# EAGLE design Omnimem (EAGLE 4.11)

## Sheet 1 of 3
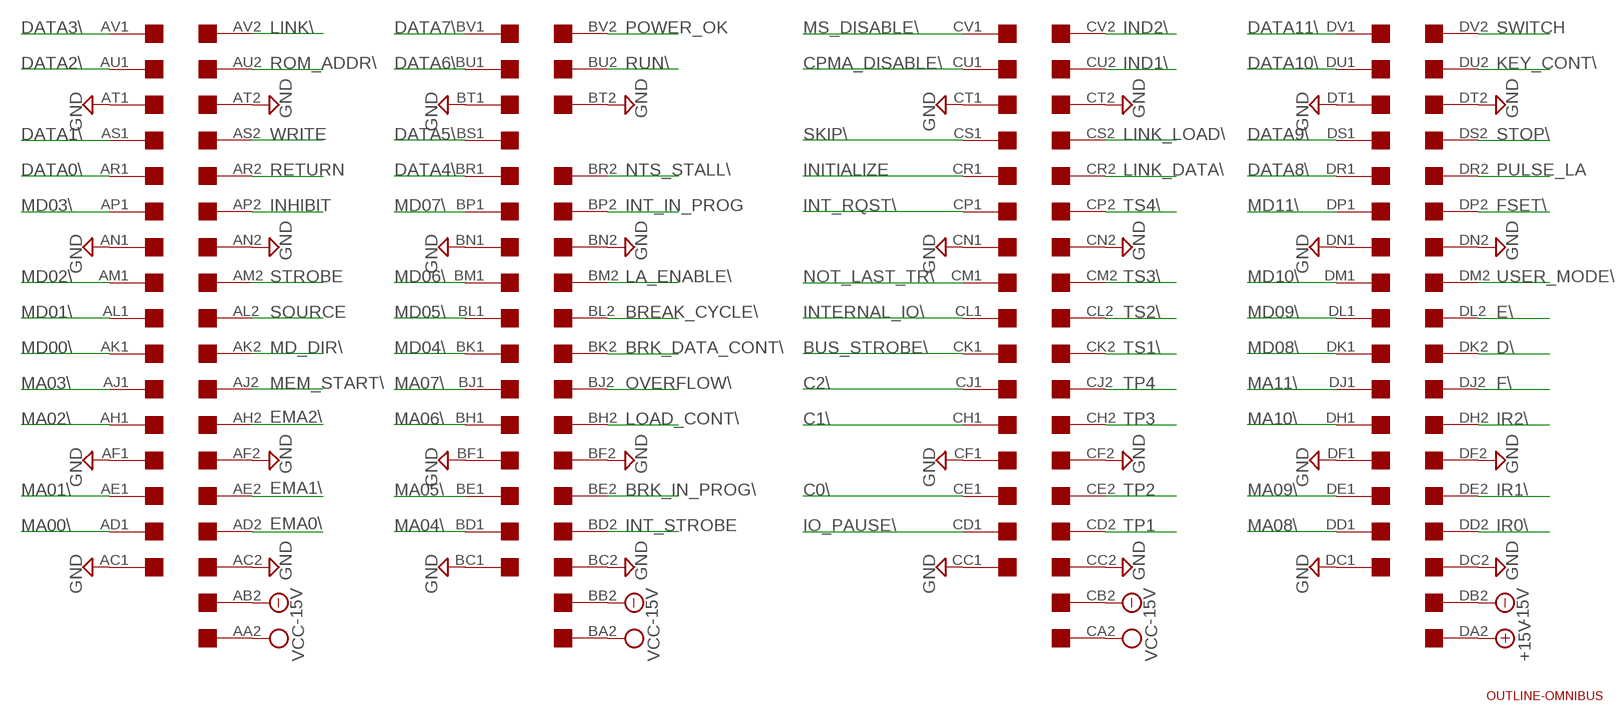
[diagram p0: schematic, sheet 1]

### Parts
U$1  OUTLINE-OMNIBUS  [OMNIBUS]
U$2  QUAD  [EDGE-CON8]

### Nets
+15V: U$2.DA2
-15V [supply]: U$2.AB2 U$2.BB2 U$2.CB2 U$2.DB2
BREAK_CYCLE\: U$2.BL2
BRK_DATA_CONT\: U$2.BK2
BRK_IN_PROG\: U$2.BE2
BUS_STROBE\: U$2.CK1
C0\: U$2.CE1
C1\: U$2.CH1
C2\: U$2.CJ1
CPMA_DISABLE\: U$2.CU1
D\: U$2.DK2
DATA0\: U$2.AR1
DATA1\: U$2.AS1
DATA2\: U$2.AU1
DATA3\: U$2.AV1
DATA4\: U$2.BR1
DATA5\: U$2.BS1
DATA6\: U$2.BU1
DATA7\: U$2.BV1
DATA8\: U$2.DR1
DATA9\: U$2.DS1
DATA10\: U$2.DU1
DATA11\: U$2.DV1
E\: U$2.DL2
EMA0\: U$2.AD2 ; also sheet 2
EMA1\: U$2.AE2 ; also sheet 2
EMA2\: U$2.AH2 ; also sheet 2
F\: U$2.DJ2
FSET\: U$2.DP2
GND [supply]: U$2.AC1 U$2.AC2 U$2.AF1 U$2.AF2 U$2.AN1 U$2.AN2 U$2.AT1 U$2.AT2 U$2.BC1 U$2.BC2 U$2.BF1 U$2.BF2 U$2.BN1 U$2.BN2 U$2.BT1 U$2.BT2 U$2.CC1 U$2.CC2 U$2.CF1 U$2.CF2 U$2.CN1 U$2.CN2 U$2.CT1 U$2.CT2 U$2.DC1 U$2.DC2 U$2.DF1 U$2.DF2 U$2.DN1 U$2.DN2 U$2.DT1 U$2.DT2 ; also sheet 2,3
IND1\: U$2.CU2
IND2\: U$2.CV2
INHIBIT: U$2.AP2
INITIALIZE: U$2.CR1
INT_IN_PROG: U$2.BP2
INT_RQST\: U$2.CP1
INT_STROBE: U$2.BD2
INTERNAL_IO\: U$2.CL1
IO_PAUSE\: U$2.CD1
IR0\: U$2.DD2
IR1\: U$2.DE2
IR2\: U$2.DH2
KEY_CONT\: U$2.DU2
LA_ENABLE\: U$2.BM2
LINK\: U$2.AV2
LINK_DATA\: U$2.CR2
LINK_LOAD\: U$2.CS2
LOAD_CONT\: U$2.BH2
MA00\: U$2.AD1 ; also sheet 2
MA01\: U$2.AE1 ; also sheet 2
MA02\: U$2.AH1 ; also sheet 2
MA03\: U$2.AJ1 ; also sheet 2
MA04\: U$2.BD1 ; also sheet 2
MA05\: U$2.BE1 ; also sheet 2
MA06\: U$2.BH1 ; also sheet 2
MA07\: U$2.BJ1 ; also sheet 2
MA08\: U$2.DD1 ; also sheet 2
MA09\: U$2.DE1 ; also sheet 2
MA10\: U$2.DH1 ; also sheet 2
MA11\: U$2.DJ1 ; also sheet 2
MD00\: U$2.AK1 ; also sheet 2
MD01\: U$2.AL1 ; also sheet 2
MD02\: U$2.AM1 ; also sheet 2
MD03\: U$2.AP1 ; also sheet 2
MD04\: U$2.BK1 ; also sheet 2
MD05\: U$2.BL1 ; also sheet 2
MD06\: U$2.BM1 ; also sheet 2
MD07\: U$2.BP1 ; also sheet 2
MD08\: U$2.DK1 ; also sheet 2
MD09\: U$2.DL1 ; also sheet 2
MD10\: U$2.DM1 ; also sheet 2
MD11\: U$2.DP1 ; also sheet 2
MD_DIR\: U$2.AK2
MEM_START\: U$2.AJ2
MS_DISABLE\: U$2.CV1
NOT_LAST_TR\: U$2.CM1
NTS_STALL\: U$2.BR2
OVERFLOW\: U$2.BJ2
POWER_OK: U$2.BV2
PULSE_LA: U$2.DR2
RETURN: U$2.AR2
ROM_ADDR\: U$2.AU2 ; also sheet 2
RUN\: U$2.BU2
SKIP\: U$2.CS1
SOURCE: U$2.AL2
STOP\: U$2.DS2
STROBE: U$2.AM2
SWITCH: U$2.DV2
TP1: U$2.CD2
TP2: U$2.CE2
TP3: U$2.CH2
TP4: U$2.CJ2
TS1\: U$2.CK2
TS2\: U$2.CL2
TS3\: U$2.CM2
TS4\: U$2.CP2
USER_MODE\: U$2.DM2
VCC [supply]: U$2.AA2 U$2.BA2 U$2.CA2 ; also sheet 2
WRITE: U$2.AS2 ; also sheet 2
Unconnected: U$2.AA1 U$2.AB1 U$2.BA1 U$2.BB1 U$2.BS2 U$2.CA1 U$2.CB1 U$2.DA1 U$2.DB1

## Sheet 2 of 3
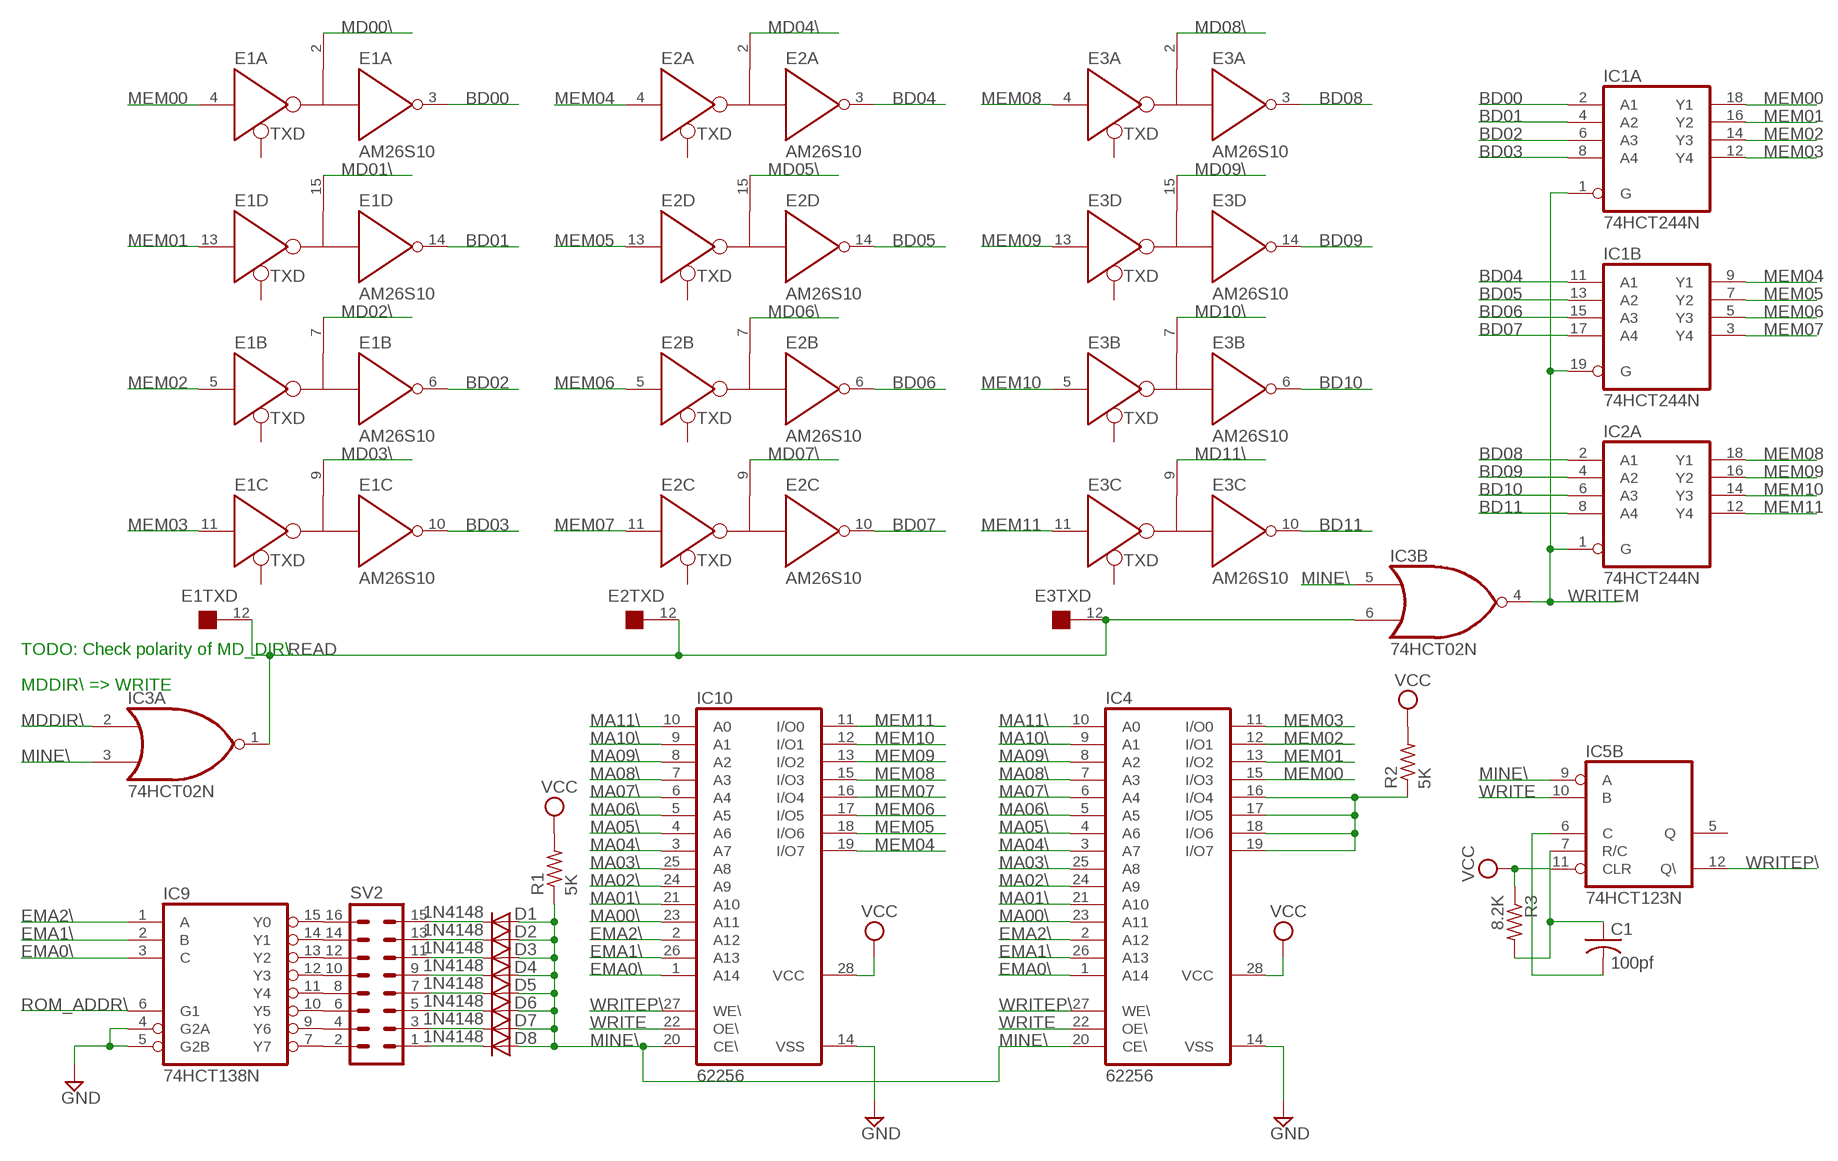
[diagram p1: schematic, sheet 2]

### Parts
C1  100pf  C-US050-025X075  [C050-025X075]
D1  1N4148  [DO35-10]
D2  1N4148  [DO35-10]
D3  1N4148  [DO35-10]
D4  1N4148  [DO35-10]
D5  1N4148  [DO35-10]
D6  1N4148  [DO35-10]
D7  1N4148  [DO35-10]
D8  1N4148  [DO35-10]
E1  AM26S10  [DIL16]
E2  AM26S10  [DIL16]
E3  AM26S10  [DIL16]
IC1  74HCT244N  [DIL20]
IC2  74HCT244N  [DIL20]
IC3  74HCT02N  [DIL14]
IC4  62256  58C256P  [DIL28-6]
IC5  74HCT123N  [DIL16]
IC9  74HCT138N  [DIL16]
IC10  62256  58C256P  [DIL28-6]
R1  5K  R-US_0207/10  [0207/10]
R2  5K  R-US_0207/10  [0207/10]
R3  8.2K  R-US_0207/10  [0207/10]
SV2  MA08-2  [MA08-2]

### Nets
BD00: E1.3(A:R) IC1.2(A:A1)
BD01: E1.14(D:R) IC1.4(A:A2)
BD02: E1.6(B:R) IC1.6(A:A3)
BD03: E1.10(C:R) IC1.8(A:A4)
BD04: E2.3(A:R) IC1.11(B:A1)
BD05: E2.14(D:R) IC1.13(B:A2)
BD06: E2.6(B:R) IC1.15(B:A3)
BD07: E2.10(C:R) IC1.17(B:A4)
BD08: E3.3(A:R) IC2.2(A:A1)
BD09: E3.14(D:R) IC2.4(A:A2)
BD10: E3.6(B:R) IC2.6(A:A3)
BD11: E3.10(C:R) IC2.8(A:A4)
EMA0\: IC4.1(A14) IC9.3(C) IC10.1(A14) ; also sheet 1
EMA1\: IC4.26(A13) IC9.2(B) IC10.26(A13) ; also sheet 1
EMA2\: IC4.2(A12) IC9.1(A) IC10.2(A12) ; also sheet 1
GND [supply]: IC4.14(VSS) IC9.4(G2A) IC9.5(G2B) IC10.14(VSS) ; also sheet 1,3
MA00\: IC4.23(A11) IC10.23(A11) ; also sheet 1
MA01\: IC4.21(A10) IC10.21(A10) ; also sheet 1
MA02\: IC4.24(A9) IC10.24(A9) ; also sheet 1
MA03\: IC4.25(A8) IC10.25(A8) ; also sheet 1
MA04\: IC4.3(A7) IC10.3(A7) ; also sheet 1
MA05\: IC4.4(A6) IC10.4(A6) ; also sheet 1
MA06\: IC4.5(A5) IC10.5(A5) ; also sheet 1
MA07\: IC4.6(A4) IC10.6(A4) ; also sheet 1
MA08\: IC4.7(A3) IC10.7(A3) ; also sheet 1
MA09\: IC4.8(A2) IC10.8(A2) ; also sheet 1
MA10\: IC4.9(A1) IC10.9(A1) ; also sheet 1
MA11\: IC4.10(A0) IC10.10(A0) ; also sheet 1
MD00\: E1.2(A:B) ; also sheet 1
MD01\: E1.15(D:B) ; also sheet 1
MD02\: E1.7(B:B) ; also sheet 1
MD03\: E1.9(C:B) ; also sheet 1
MD04\: E2.2(A:B) ; also sheet 1
MD05\: E2.15(D:B) ; also sheet 1
MD06\: E2.7(B:B) ; also sheet 1
MD07\: E2.9(C:B) ; also sheet 1
MD08\: E3.2(A:B) ; also sheet 1
MD09\: E3.15(D:B) ; also sheet 1
MD10\: E3.7(B:B) ; also sheet 1
MD11\: E3.9(C:B) ; also sheet 1
MDDIR\: IC3.2(A:I0)
MEM00: E1.4(A:D) IC1.18(A:Y1) IC4.15(I/O3)
MEM01: E1.13(D:D) IC1.16(A:Y2) IC4.13(I/O2)
MEM02: E1.5(B:D) IC1.14(A:Y3) IC4.12(I/O1)
MEM03: E1.11(C:D) IC1.12(A:Y4) IC4.11(I/O0)
MEM04: E2.4(A:D) IC1.9(B:Y1) IC10.19(I/O7)
MEM05: E2.13(D:D) IC1.7(B:Y2) IC10.18(I/O6)
MEM06: E2.5(B:D) IC1.5(B:Y3) IC10.17(I/O5)
MEM07: E2.11(C:D) IC1.3(B:Y4) IC10.16(I/O4)
MEM08: E3.4(A:D) IC2.18(A:Y1) IC10.15(I/O3)
MEM09: E3.13(D:D) IC2.16(A:Y2) IC10.13(I/O2)
MEM10: E3.5(B:D) IC2.14(A:Y3) IC10.12(I/O1)
MEM11: E3.11(C:D) IC2.12(A:Y4) IC10.11(I/O0)
MINE\: D1.A D2.A D3.A D4.A D5.A D6.A D7.A D8.A IC3.3(A:I1) IC3.5(B:I0) IC4.20(CE\) IC5.9(B:A) IC10.20(CE\) R1.1
N$1: IC9.7(Y7) SV2.2
N$18: IC9.9(Y6) SV2.4
N$19: IC9.10(Y5) SV2.6
N$20: IC9.11(Y4) SV2.8
N$21: IC9.12(Y3) SV2.10
N$22: IC9.13(Y2) SV2.12
N$23: IC9.14(Y1) SV2.14
N$24: IC9.15(Y0) SV2.16
N$25: C1.1 IC5.7(B:R/C) R3.2
N$26: D8.C SV2.1
N$27: D7.C SV2.3
N$28: D6.C SV2.5
N$29: D5.C SV2.7
N$30: D4.C SV2.9
N$31: D3.C SV2.11
N$32: D2.C SV2.13
N$33: D1.C SV2.15
N$34: C1.2 IC5.6(B:C)
N$35: IC4.16(I/O4) IC4.17(I/O5) IC4.18(I/O6) IC4.19(I/O7) R2.1
READ: E1.12(TXD:TXD) E2.12(TXD:TXD) E3.12(TXD:TXD) IC3.1(A:O) IC3.6(B:I1)
ROM_ADDR\: IC9.6(G1) ; also sheet 1
VCC [supply]: IC4.28(VCC) IC5.11(B:CLR) IC10.28(VCC) R1.2 R2.2 R3.1 ; also sheet 1
WRITE: IC4.22(OE\) IC5.10(B:B) IC10.22(OE\) ; also sheet 1
WRITEM: IC1.1(A:G) IC1.19(B:G) IC2.1(A:G) IC3.4(B:O)
WRITEP\: IC4.27(WE\) IC5.12(B:Q\) IC10.27(WE\)
Unconnected: IC2.3(B:Y4) IC2.5(B:Y3) IC2.7(B:Y2) IC2.9(B:Y1) IC2.11(B:A1) IC2.13(B:A2) IC2.15(B:A3) IC2.17(B:A4) IC2.19(B:G) IC3.8(C:I0) IC3.9(C:I1) IC3.10(C:O) IC3.11(D:I0) IC3.12(D:I1) IC3.13(D:O) IC5.1(A:A) IC5.2(A:B) IC5.3(A:CLR) IC5.4(A:Q\) IC5.5(B:Q) IC5.13(A:Q) IC5.14(A:C) IC5.15(A:R/C)

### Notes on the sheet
- TODO: Check polarity of MD_DIR\.
- MDDIR\ => WRITE

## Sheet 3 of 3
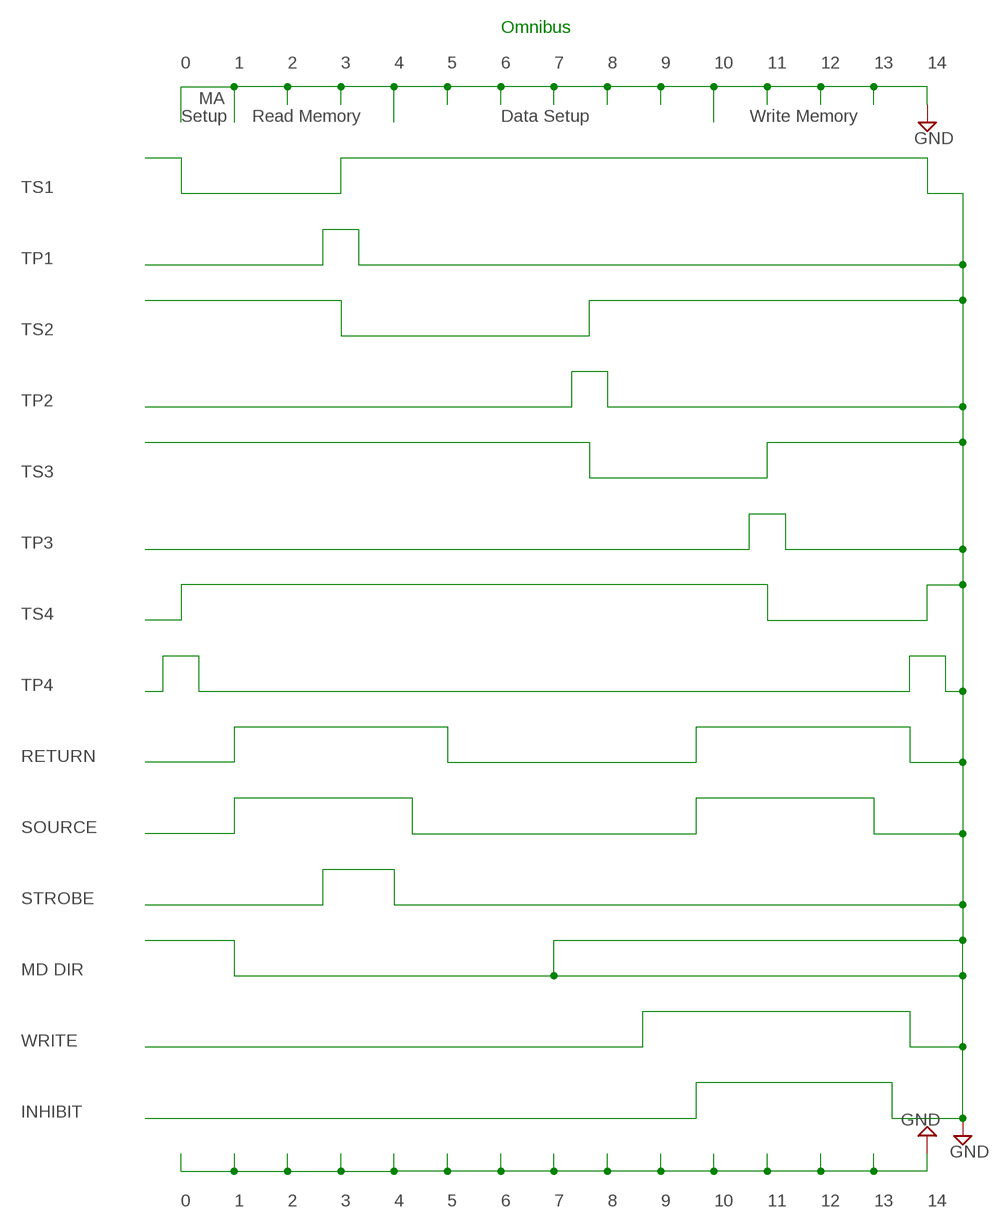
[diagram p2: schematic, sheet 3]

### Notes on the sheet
- Omnibus
- 0 | 1 | 2 | 3 | 4 | 5 | 6 | 7 | 8 | 9 | 10 | 11 | 12 | 13 | 14
- MA
- Setup | Read Memory | Data Setup | Write Memory
- TS1
- TP1
- TS2
- TP2
- TS3
- TP3
- TS4
- TP4
- RETURN
- SOURCE
- STROBE
- MD DIR
- WRITE
- INHIBIT
- 0 | 1 | 2 | 3 | 4 | 5 | 6 | 7 | 8 | 9 | 10 | 11 | 12 | 13 | 14

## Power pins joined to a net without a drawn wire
GND: E1.1(GND:GND) E1.8(PWR:GND) E2.1(GND:GND) E2.8(PWR:GND) E3.1(GND:GND) E3.8(PWR:GND) IC1.10(P:GND) IC2.10(P:GND) IC3.7(P:GND) IC5.8(P:GND) IC9.8(GND)
VCC: E1.16(PWR:VCC) E2.16(PWR:VCC) E3.16(PWR:VCC) IC1.20(P:VCC) IC2.20(P:VCC) IC3.14(P:VCC) IC5.16(P:VCC) IC9.16(VCC)

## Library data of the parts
C1 = rcl:C-US: CAPACITOR, American symbol
D1-D8 = diode:1N4148: DIODE
E1-E3 = dec-con:AM26S10: Bus Transceiver
IC1 IC2 = 74xx-jameco:74*244: Octal BUFFER and LINE DRIVER, 3-state
IC3 = 74xx-jameco:74*02: Quad 2-input NOR gate
IC4 IC10 = memory-hitachi:58C256P: MEMORY
IC5 = 74xx-jameco:74*123: Retriggerable monostable MULTIVIBRATOR
IC9 = 74xx-jameco:74*138: 3-line to 8-line DECODER/DEMULTIPLEXER
R1-R3 = rcl:R-US_: RESISTOR, American symbol
SV2 = con-lstb:MA08-2: PIN HEADER
U$1 = dec-con:OUTLINE-*: Board outlines for DEC boards.
U$2 = dec-con:QUAD: Quad-Height DEC board

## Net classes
1 supply: width 0.762 mm

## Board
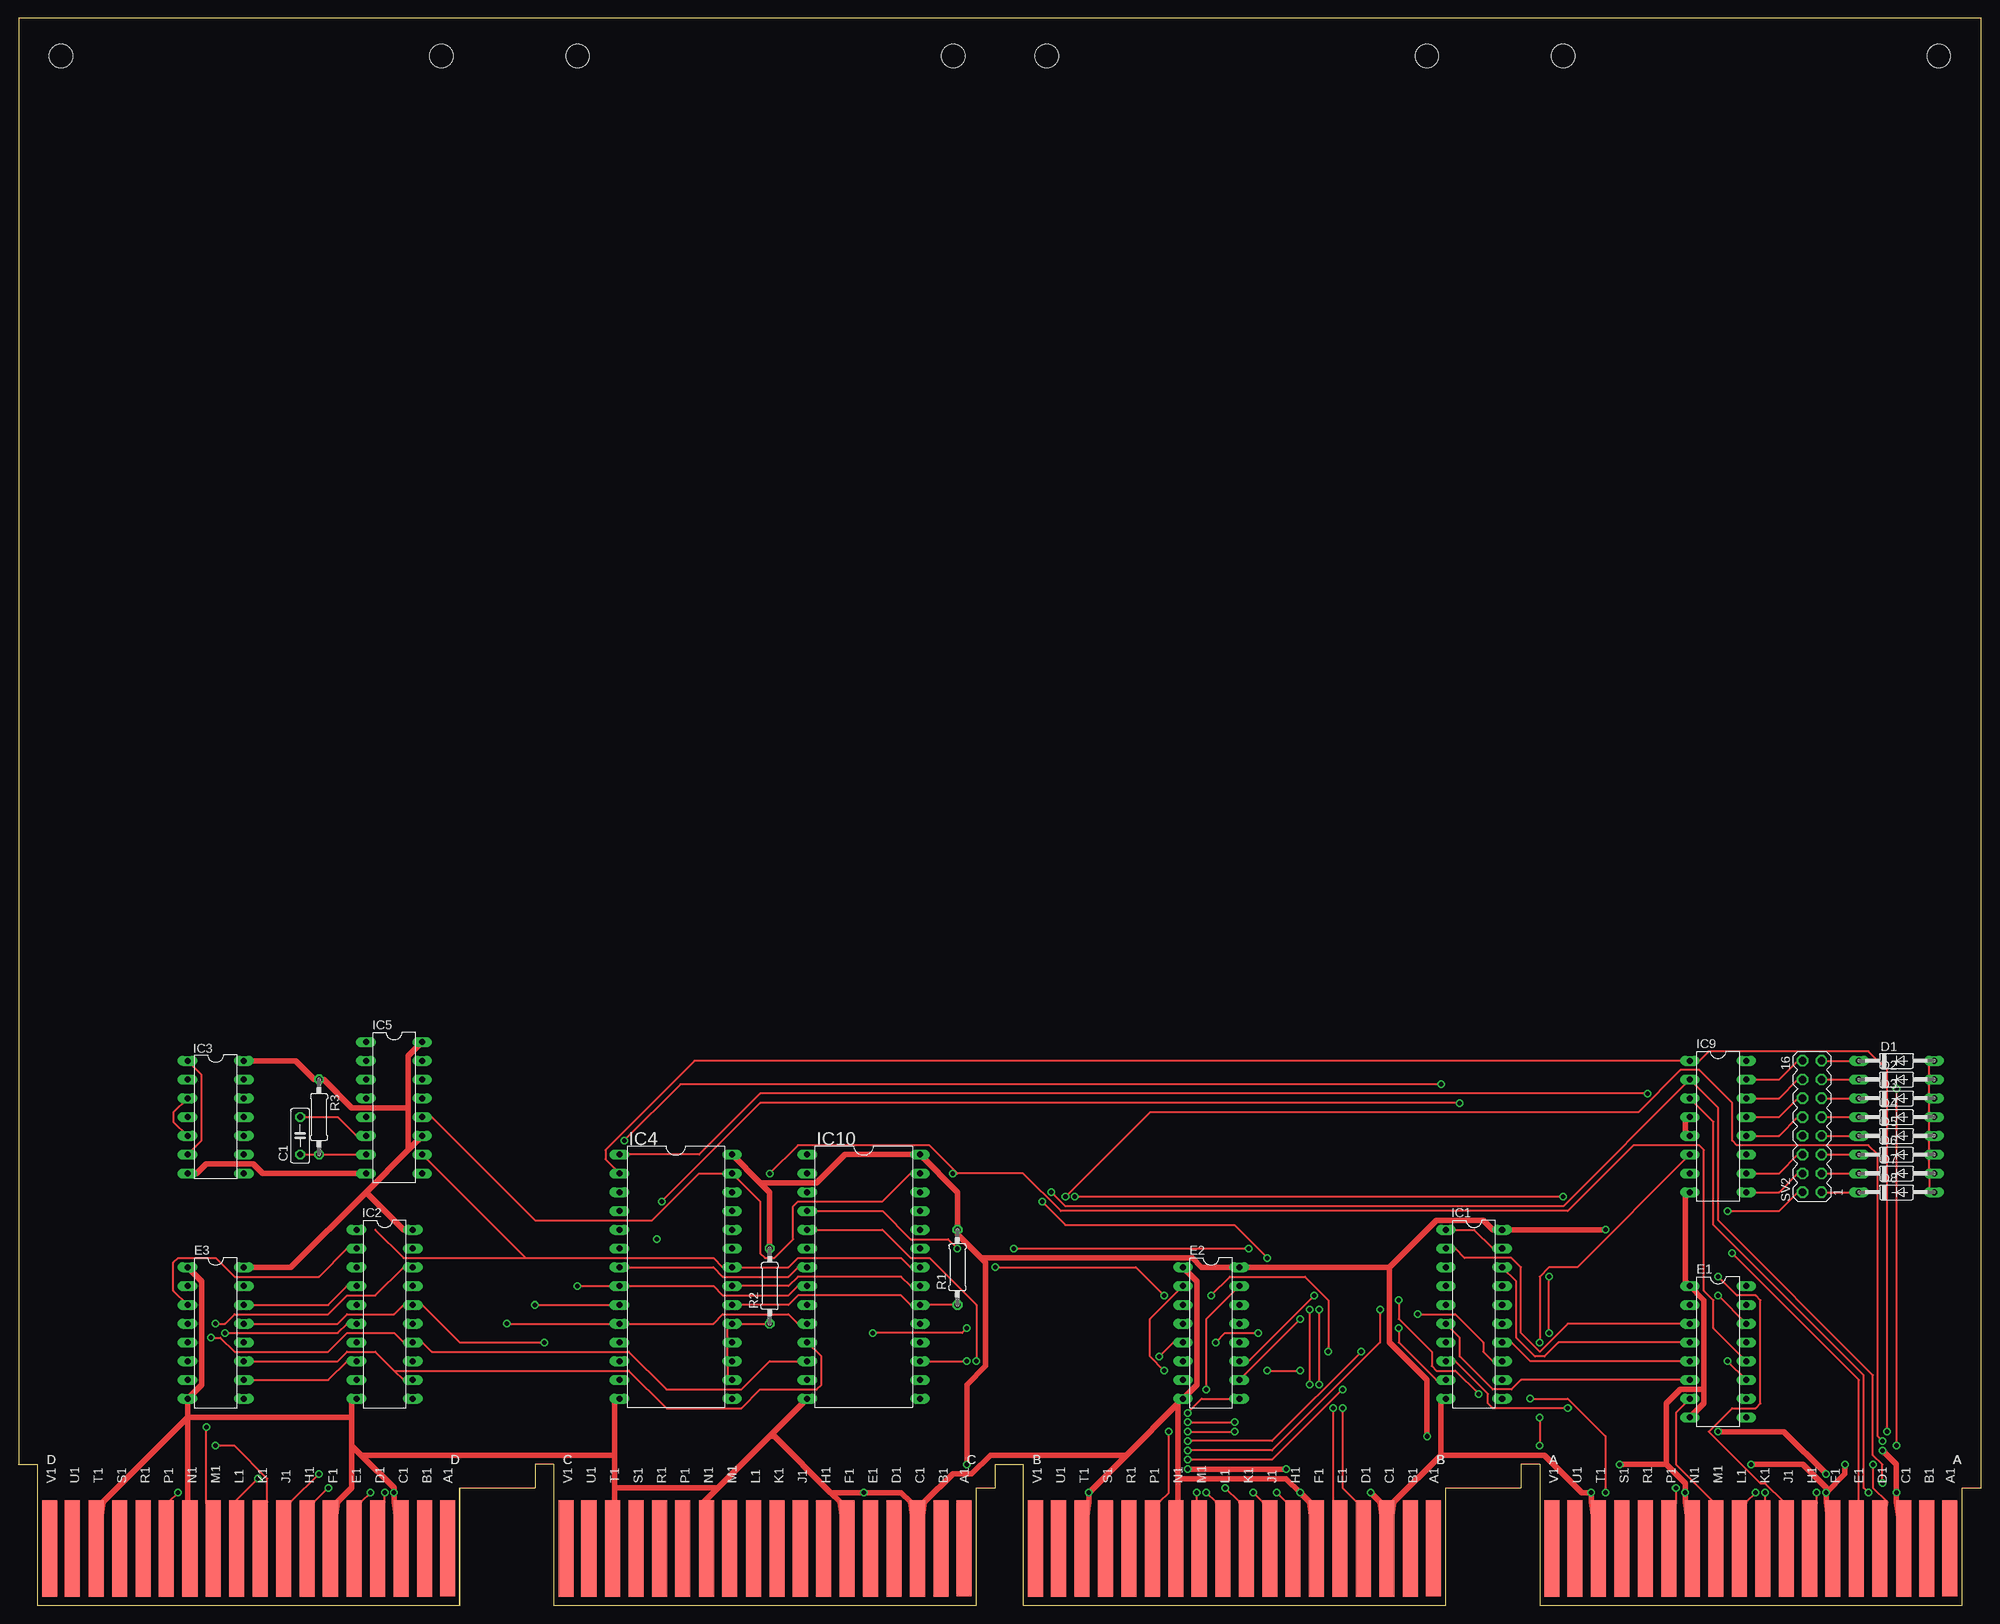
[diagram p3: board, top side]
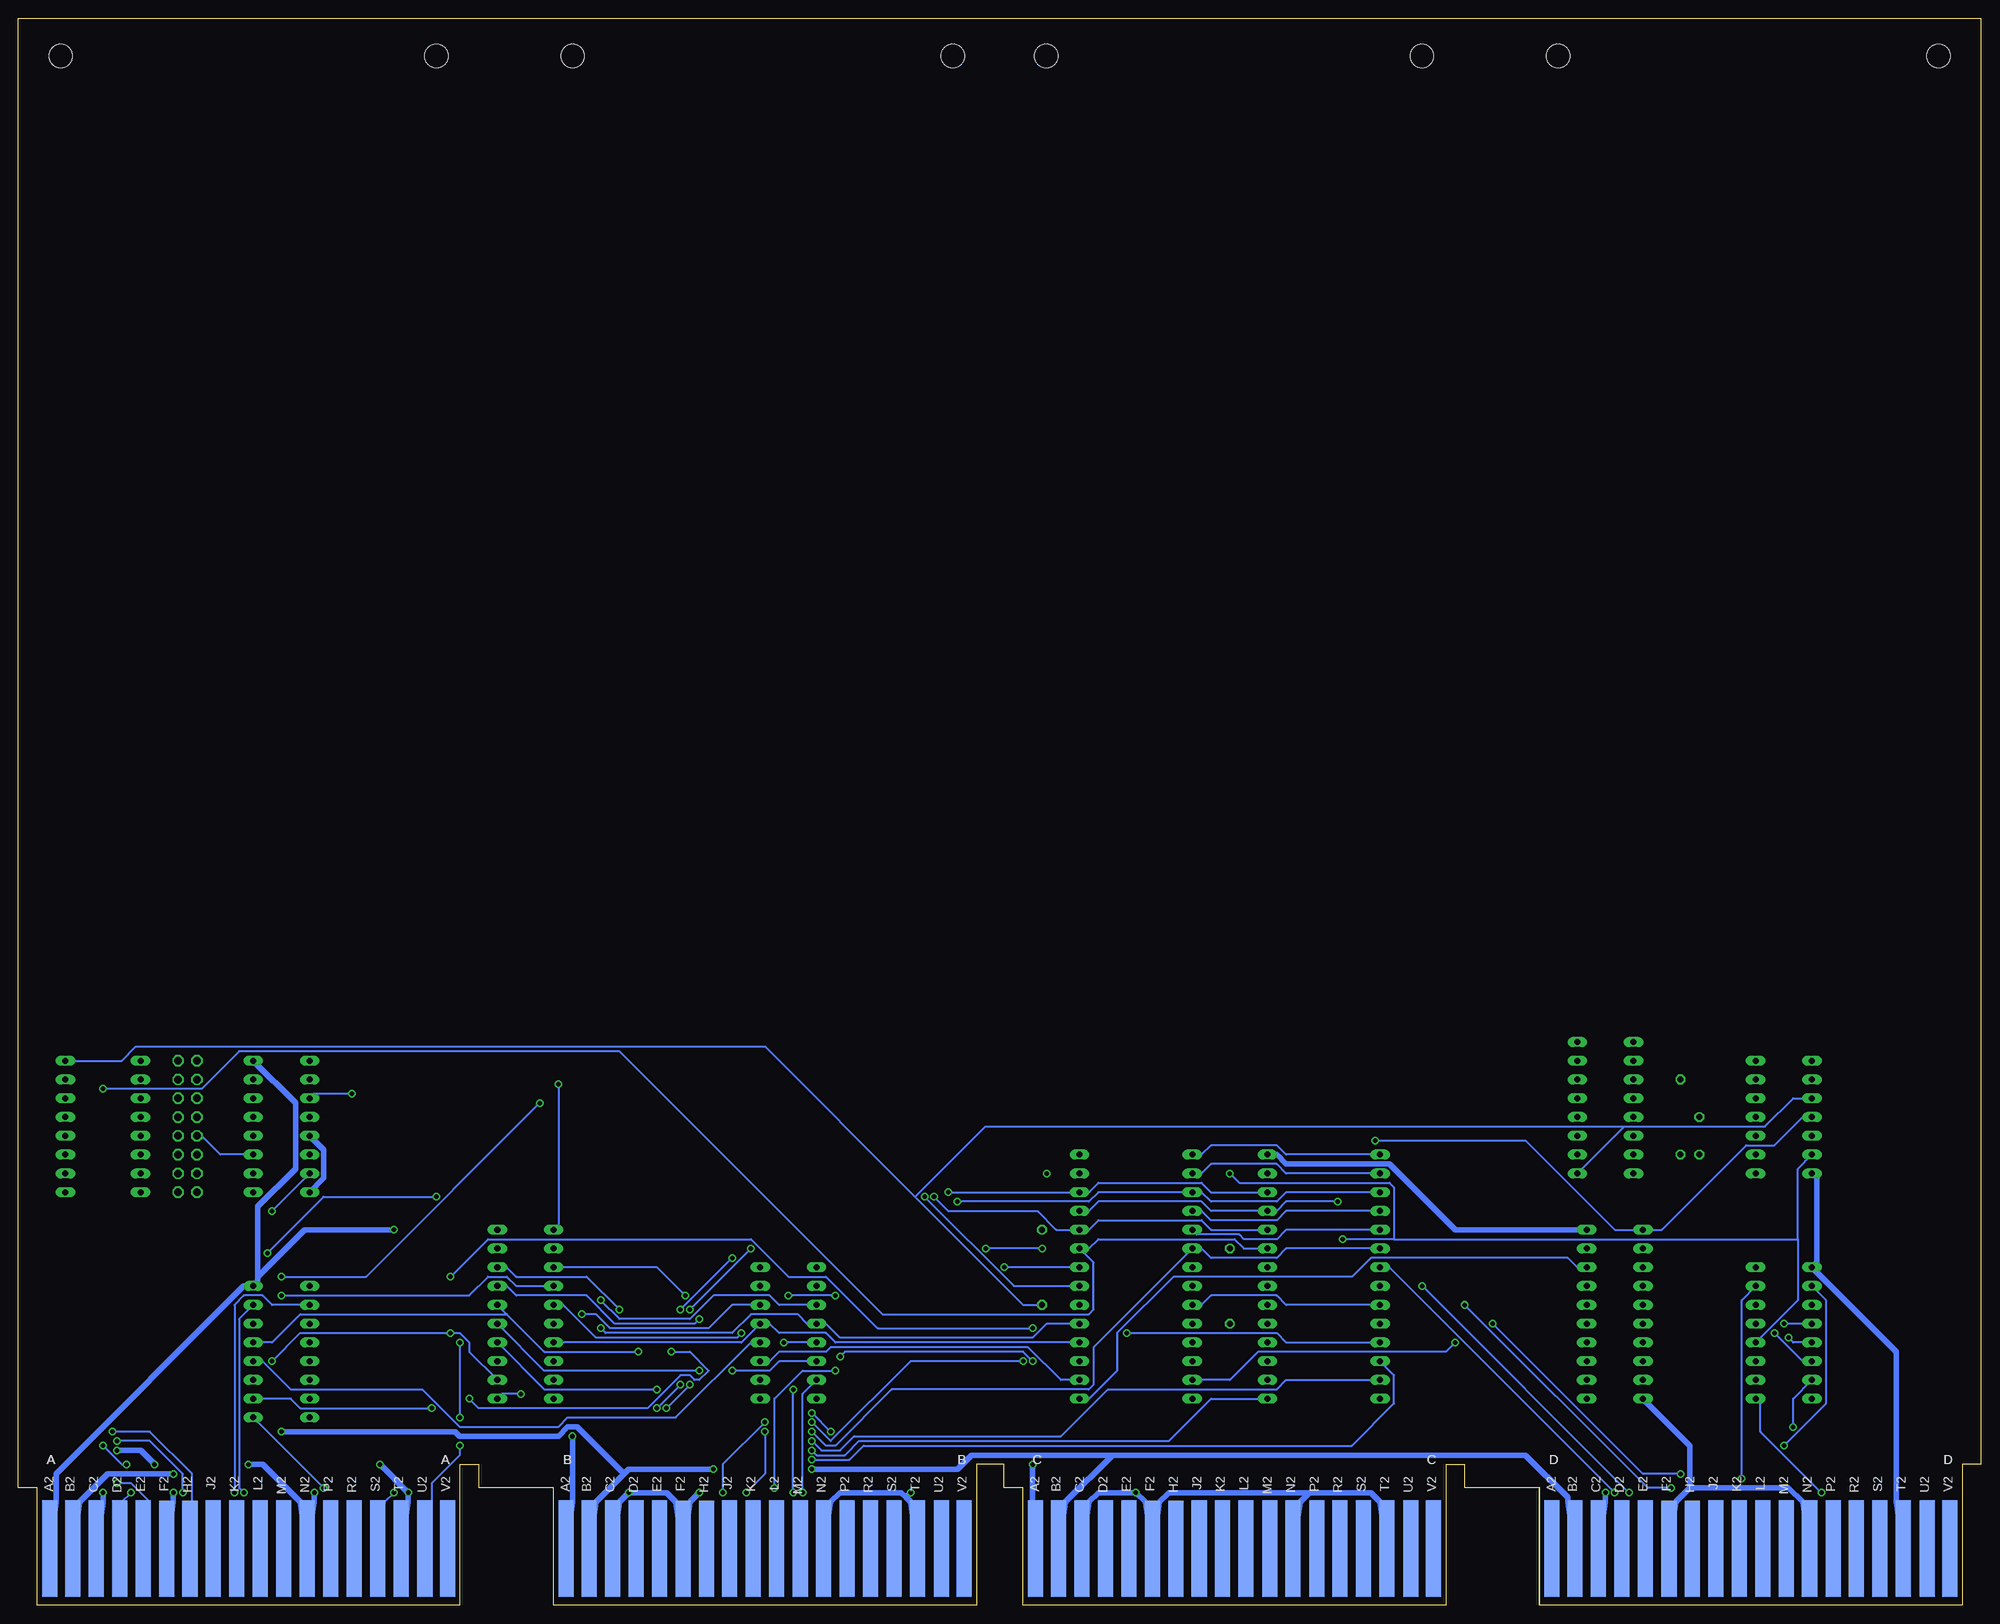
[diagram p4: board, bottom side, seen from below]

Size 265.43 x 214.63 mm. Coordinates in mm from the lower left corner, seen from the top.
Copper layers (1*16): Top 0.035mm / dielectric 1.5mm / Bottom 0.035mm
Design rules "default": minimum track width 10mil, minimum drill 24mil, track to track 8mil, track to pad 8mil, pad to pad 8mil, via to via 8mil, smd to smd 8mil, copper to edge 25mil, drill to drill 8mil, minimum pad ring 10mil, minimum via ring 8mil, stop-mask expansion 4mil, vias tented up to drill 0mil, thermal gap 10mil

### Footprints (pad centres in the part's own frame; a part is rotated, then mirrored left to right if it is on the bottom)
C050-025X075 = drill 0.813 octagon: 1 -2.54,0; 2 2.54,0
DO35-10 = drill 0.813 long: A 5.08,0; C -5.08,0
DIL16 = drill 0.813 long: 1 -8.89,-3.81; 2 -6.35,-3.81; 3 -3.81,-3.81; 4 -1.27,-3.81; 5 1.27,-3.81; 6 3.81,-3.81; 7 6.35,-3.81; 8 8.89,-3.81; 9 8.89,3.81; 10 6.35,3.81; 11 3.81,3.81; 12 1.27,3.81; 13 -1.27,3.81; 14 -3.81,3.81; 15 -6.35,3.81; 16 -8.89,3.81
DIL20 = drill 0.813 long: 1 -11.43,-3.81; 2 -8.89,-3.81; 3 -6.35,-3.81; 4 -3.81,-3.81; 5 -1.27,-3.81; 6 1.27,-3.81; 7 3.81,-3.81; 8 6.35,-3.81; 9 8.89,-3.81; 10 11.43,-3.81; 11 11.43,3.81; 12 8.89,3.81; 13 6.35,3.81; 14 3.81,3.81; 15 1.27,3.81; 16 -1.27,3.81; 17 -3.81,3.81; 18 -6.35,3.81; 19 -8.89,3.81; 20 -11.43,3.81
DIL14 = drill 0.813 long: 1 -7.62,-3.81; 2 -5.08,-3.81; 3 -2.54,-3.81; 4 0,-3.81; 5 2.54,-3.81; 6 5.08,-3.81; 7 7.62,-3.81; 8 7.62,3.81; 9 5.08,3.81; 10 2.54,3.81; 11 0,3.81; 12 -2.54,3.81; 13 -5.08,3.81; 14 -7.62,3.81
DIL28-6 = drill 0.813 long: 1 -16.51,-7.62; 2 -13.97,-7.62; 3 -11.43,-7.62; 4 -8.89,-7.62; 5 -6.35,-7.62; 6 -3.81,-7.62; 7 -1.27,-7.62; 8 1.27,-7.62; 9 3.81,-7.62; 10 6.35,-7.62; 11 8.89,-7.62; 12 11.43,-7.62; 13 13.97,-7.62; 14 16.51,-7.62; 15 16.51,7.62; 16 13.97,7.62; 17 11.43,7.62; 18 8.89,7.62; 19 6.35,7.62; 20 3.81,7.62; 21 1.27,7.62; 22 -1.27,7.62; 23 -3.81,7.62; 24 -6.35,7.62; 25 -8.89,7.62; 26 -11.43,7.62; 27 -13.97,7.62; 28 -16.51,7.62
0207/10 = drill 0.813 octagon: 1 -5.08,0; 2 5.08,0
MA08-2 = drill 1.016 octagon: 1 -8.89,-1.27; 2 -8.89,1.27; 3 -6.35,-1.27; 4 -6.35,1.27; 5 -3.81,-1.27; 6 -3.81,1.27; 7 -1.27,-1.27; 8 -1.27,1.27; 9 1.27,-1.27; 10 1.27,1.27; 11 3.81,-1.27; 12 3.81,1.27; 13 6.35,-1.27; 14 6.35,1.27; 15 8.89,-1.27; 16 8.89,1.27
OMNIBUS = hole 3.175: 208.915,209.55; 259.715,209.55; 190.5,209.55; 139.065,209.55; 75.616,209.55; 126.416,209.55; 57.201,209.55; 5.766,209.55
EDGE-CON8 = smd 2.032 x 13.017: AA1 261.223,7.709; AB1 258.118,7.684; AC1 254.956,7.684; AD1 251.765,7.684; AE1 248.59,7.693; AF1 245.389,7.668; AH1 242.24,7.668; AJ1 239.09,7.668; AK1 235.915,7.668; AL1 232.74,7.693; AM1 229.54,7.693; AN1 226.39,7.693; AP1 223.19,7.668; AR1 220.04,7.668; AS1 216.865,7.693; AT1 213.69,7.693; AU1 210.49,7.693; AV1 207.404,7.668; BA1 191.373,7.709; BB1 188.268,7.684; BC1 185.106,7.684; BD1 181.915,7.684; BE1 178.74,7.693; BF1 175.539,7.668; BH1 172.39,7.668; BJ1 169.24,7.668; BK1 166.065,7.668; BL1 162.89,7.693; BM1 159.69,7.693; BN1 156.54,7.693; BP1 153.34,7.668; BR1 150.19,7.668; BS1 147.015,7.693; BT1 143.84,7.693; BU1 140.64,7.693; BV1 137.554,7.668; CA1 127.873,7.709; CB1 124.768,7.684; CC1 121.606,7.684; CD1 118.415,7.684; CE1 115.24,7.693; CF1 112.039,7.668; CH1 108.89,7.668; CJ1 105.74,7.668; CK1 102.565,7.668; CL1 99.39,7.693; CM1 96.19,7.693; CN1 93.04,7.693; CP1 89.84,7.668; CR1 86.69,7.668; CS1 83.515,7.693; CT1 80.34,7.693; CU1 77.14,7.693; CV1 74.054,7.668; DA1 58.023,7.709; DB1 54.918,7.684; DC1 51.756,7.684; DD1 48.565,7.684; DE1 45.39,7.693; DF1 42.189,7.668; DH1 39.04,7.668; DJ1 35.89,7.668; DK1 32.715,7.668; DL1 29.54,7.693; DM1 26.34,7.693; DN1 23.19,7.693; DP1 19.99,7.668; DR1 16.84,7.668; DS1 13.665,7.693; DT1 10.49,7.693; DU1 7.29,7.693; DV1 4.204,7.668 | smd 2.032 x 13.017 bottom: AA2 261.223,7.69; AB2 258.102,7.668; AC2 254.94,7.668; AD2 251.765,7.693; AE2 248.59,7.693; AF2 245.389,7.642; AH2 242.24,7.642; AJ2 239.09,7.668; AK2 235.915,7.668; AL2 232.74,7.693; AM2 229.54,7.693; AN2 226.39,7.693; AP2 223.19,7.668; AR2 220.04,7.668; AS2 216.865,7.693; AT2 213.69,7.693; AU2 210.464,7.693; AV2 207.404,7.668; BA2 191.373,7.69; BB2 188.252,7.668; BC2 185.09,7.668; BD2 181.915,7.693; BE2 178.74,7.693; BF2 175.539,7.642; BH2 172.39,7.642; BJ2 169.24,7.668; BK2 166.065,7.668; BL2 162.89,7.693; BM2 159.69,7.693; BN2 156.54,7.693; BP2 153.34,7.668; BR2 150.19,7.668; BS2 147.015,7.693; BT2 143.84,7.693; BU2 140.614,7.693; BV2 137.554,7.668; CA2 127.873,7.69; CB2 124.752,7.668; CC2 121.59,7.668; CD2 118.415,7.693; CE2 115.24,7.693; CF2 112.039,7.642; CH2 108.89,7.642; CJ2 105.74,7.668; CK2 102.565,7.668; CL2 99.39,7.693; CM2 96.19,7.693; CN2 93.04,7.693; CP2 89.84,7.668; CR2 86.69,7.668; CS2 83.515,7.693; CT2 80.34,7.693; CU2 77.114,7.693; CV2 74.054,7.668; DA2 58.023,7.69; DB2 54.902,7.668; DC2 51.74,7.668; DD2 48.565,7.693; DE2 45.39,7.693; DF2 42.189,7.642; DH2 39.04,7.642; DJ2 35.89,7.668; DK2 32.715,7.668; DL2 29.54,7.693; DM2 26.34,7.693; DN2 23.19,7.693; DP2 19.99,7.668; DR2 16.84,7.668; DS2 13.665,7.693; DT2 10.49,7.693; DU2 7.264,7.693; DV2 4.204,7.668

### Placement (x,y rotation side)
C1  38.1,63.5 90 top
D1  254,73.66 0 top
D2  254,71.12 0 top
D3  254,68.58 0 top
D4  254,66.04 0 top
D5  254,63.5 0 top
D6  254,60.96 0 top
D7  254,58.42 0 top
D8  254,55.88 0 top
E1  229.87,34.29 270 top
E2  161.29,36.83 270 top
E3  26.67,36.83 270 top
IC1  196.85,39.37 270 top
IC2  49.53,39.37 270 top
IC3  26.67,66.04 270 top
IC4  88.9,44.45 270 top
IC5  50.8,67.31 270 top
IC9  229.87,64.77 270 top
IC10  114.3,44.45 270 top
R1  127,45.72 90 top
R2  101.6,43.18 90 top
R3  40.64,66.04 270 top
SV2  242.57,64.77 90 top
U$1  0,0 0 top
U$2  0,0 0 top

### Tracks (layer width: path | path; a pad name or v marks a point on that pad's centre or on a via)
-15V  (via drill 0.61)
  Top 0.762: v171.45,18.42 v158.12,18.42 | v244.47,17.78 238.76,23.5 v229.87,23.5
  Bottom 0.762: 117.47,20.32 61.59,20.32 55.88,14.61 55.88,13.97 U$2.DB2 | 117.47,20.32 123.83,13.97 U$2.CB2 | 183.51,17.78 182.88,18.42 v171.45,18.42 | 183.51,17.78 187.32,13.97 U$2.BB2 | v158.12,18.42 138.43,18.42 136.53,20.32 117.47,20.32 | v244.47,17.78 253.37,17.78 257.18,13.97 U$2.AB2 | v229.87,23.5 206.38,23.5 205.74,22.86 192.41,22.86 191.13,24.13 189.87,24.13 183.51,17.78
BD00
  Top 0.254: E1.3 209.55,38.1 205.74,34.29 203.2,36.83 203.2,45.72 201.93,46.99 195.58,46.99 194.31,48.26 IC1.2
BD01  (via drill 0.61)
  Top 0.254: v229.87,41.91 E1.14
  Bottom 0.254: v229.87,41.91 204.47,41.91 201.93,44.45 199.39,44.45 198.12,43.18 IC1.4
BD02
  Top 0.254: E1.6 203.2,30.48 201.93,29.21 199.39,29.21 194.94,33.66 194.94,36.2 IC1.6
BD03  (via drill 0.61)
  Top 0.254: v209.55,26.67 199.39,26.67 198.75,27.31 198.75,28.58 194.31,33.02 IC1.8
  Bottom 0.254: v209.55,26.67 227.33,26.67 228.6,27.94 E1.10
BD04  (via drill 0.61)
  Top 0.254: v186.69,41.28 186.69,38.74 191.13,34.29 191.13,32.39 191.77,31.75 194.31,31.75 v197.49,28.58
  Bottom 0.254: v186.69,41.28 184.15,38.74 174.62,38.74 171.45,41.91 163.83,41.91 162.56,40.64 E2.3 | v197.49,28.58 200.03,28.58 IC1.11
BD05  (via drill 0.61)
  Top 0.254: v189.23,39.37 194.31,39.37 198.12,35.56 198.12,34.29 199.39,33.02 IC1.13
  Bottom 0.254: v189.23,39.37 187.32,39.37 185.42,37.47 172.09,37.47 168.91,40.64 E2.14
BD06  (via drill 0.61)
  Top 0.254: v168.91,31.75 v173.35,31.75
  Bottom 0.254: v168.91,31.75 163.83,31.75 162.56,33.02 E2.6 | v173.35,31.75 194.31,31.75 IC1.15
BD07  (via drill 0.61)
  Top 0.254: E2.10 v173.35,38.74
  Bottom 0.254: v173.35,38.74 173.99,38.1 184.78,38.1 188.59,41.91 198.12,41.91 199.39,43.18 IC1.17
BD08
  Top 0.254: E3.3 20.95,42.55 20.95,46.36 21.59,46.99 26.67,46.99 29.21,44.45 40.64,44.45 44.45,48.26 IC2.2
BD09
  Top 0.254: E3.14 41.91,40.64 44.45,43.18 IC2.4
BD10  (via drill 0.61)
  Top 0.254: v27.94,36.83 43.18,36.83 44.45,38.1 IC2.6
  Bottom 0.254: v27.94,36.83 24.13,33.02 E3.6
BD11
  Top 0.254: E3.10 41.91,30.48 44.45,33.02 IC2.8
EMA0\  (via drill 0.61)
  Top 0.254: v250.19,15.24 249.56,15.88 249.56,31.12 229.24,51.44 229.24,65.41 IC9.3 | v220.34,69.22 100.33,69.22 92.08,60.96 IC4.1
  Bottom 0.254: IC4.1 93.98,60.96 95.25,62.23 104.14,62.23 105.41,60.96 IC10.1 | v250.19,15.24 251.46,13.97 U$2.AD2 | v220.34,69.22 225.43,69.22 IC9.3
EMA1\  (via drill 0.61)
  Top 0.254: v252.09,16.51 252.09,19.05 250.82,20.32 250.82,31.12 229.87,52.07 229.87,67.31 IC9.2 208.91,53.98 141.6,53.98 v139.7,55.88
  Bottom 0.254: IC4.26 104.14,55.88 105.41,57.15 119.38,57.15 120.65,55.88 IC10.26 v139.7,55.88 | v252.09,16.51 250.19,16.51 247.65,13.97 U$2.AE2
EMA2\  (via drill 0.61)
  Top 0.254: IC4.2 79.38,60.33 79.38,61.6 91.44,73.66 IC9.1 227.33,73.66 228.6,74.93 250.19,74.93 252.73,72.39 v252.73,23.5
  Bottom 0.254: IC4.2 93.98,58.42 95.25,59.69 104.14,59.69 105.41,58.42 IC10.2 | v252.73,23.5 247.65,23.5 241.94,17.78 241.94,13.97 U$2.AH2
GND  (via drill 0.61)
  Top 0.762: 80.64,15.88 80.64,13.97 U$2.CT2 | 80.64,15.88 80.64,20.32 | 80.64,20.32 80.64,27.31 IC4.14 | 94.61,15.88 92.71,13.97 U$2.CN2 | 101.6,22.86 94.61,15.88 | 101.6,22.86 IC10.14 | 109.86,15.24 102.23,22.86 101.6,22.86 | 109.86,15.24 111.12,13.97 U$2.CF1 | 109.86,15.24 v114.3,15.24 119.38,15.24 120.65,13.97 U$2.CC1 122.56,13.97 126.36,17.78 128.91,17.78 131.44,20.32 149.86,20.32 | 94.61,15.88 80.64,15.88 | U$2.DC1 50.8,13.97 v50.8,15.24 50.8,15.88 46.35,20.32 | 45.09,21.59 45.09,15.88 43.18,13.97 U$2.DF1 | 45.09,21.59 45.09,25.4 | 45.09,25.4 45.09,27.31 IC2.10 | 46.35,20.32 45.09,21.59 | 22.86,25.4 22.86,13.97 U$2.DN2 | 22.86,25.4 E3.8 24.77,29.85 24.77,43.82 E3.1 | 22.86,25.4 11.43,13.97 U$2.DT2 | IC3.7 24.13,58.42 25.4,59.69 31.75,59.69 33.02,58.42 IC5.8 | 45.09,25.4 22.86,25.4 | 80.64,20.32 46.35,20.32 | U$2.AC1 254,13.97 v254,15.24 254,19.05 v252.09,20.96 | v244.47,15.24 244.47,13.97 U$2.AF1 | U$2.AN2 225.43,13.97 v225.43,15.24 225.43,16.51 222.88,19.05 | IC9.5 225.43,64.14 225.43,65.41 IC9.4 | 227.97,29.21 227.97,41.28 E1.1 225.43,43.82 225.43,55.25 IC9.8 | 227.97,29.21 227.97,27.31 E1.8 | 222.88,19.05 222.88,27.31 224.79,29.21 227.97,29.21 | v244.47,15.24 244.47,15.88 241.3,19.05 v234.31,19.05 | v247.01,19.05 247.01,17.78 v244.47,15.24 | U$2.AT2 212.72,13.97 v212.72,15.24 211.46,15.24 206.38,20.32 192.41,20.32 | 192.41,20.32 192.41,27.31 IC1.10 | 192.41,20.32 186.06,13.97 U$2.BC1 184.15,13.97 v182.88,15.24 | 156.84,17.15 156.84,13.97 U$2.BN2 | 156.84,17.15 156.84,27.31 | E2.1 159.38,43.82 159.38,29.85 E2.8 156.84,27.31 | 156.84,27.31 149.86,20.32 | 149.86,20.32 v144.78,15.24 144.78,13.97 U$2.BT2
  Top 0.762: 156.84,17.15 171.45,17.15 v173.35,15.24 174.62,13.97 U$2.BF1 | 222.88,19.05 v216.53,19.05
  Bottom 0.762: U$2.CC2 120.65,13.97 119.38,15.24 v114.3,15.24 113.03,13.97 U$2.CF2 111.12,13.97 109.86,15.24 90.81,15.24 | 90.81,15.24 82.55,15.24 81.28,13.97 U$2.CT2 | 90.81,15.24 92.08,13.97 U$2.CN2 | v50.8,15.24 50.8,13.97 U$2.DC2 | 39.37,15.88 41.27,13.97 U$2.DF2 | 39.37,15.88 39.37,21.59 IC2.10 | 39.37,15.88 26.04,15.88 24.13,13.97 U$2.DN2 | IC3.7 22.23,57.79 22.23,46.36 E3.1 11.43,34.29 11.43,13.97 U$2.DT2 | v254,15.24 254,13.97 U$2.AC2 | v244.47,15.24 244.47,13.97 U$2.AF2 | v225.43,15.24 225.43,13.97 U$2.AN2 227.33,13.97 232.41,19.05 v234.31,19.05 | IC9.5 224.16,61.6 224.16,57.79 IC9.8 | v252.09,20.96 248.92,20.96 v247.01,19.05 | U$2.AT2 212.72,13.97 v212.72,15.24 v216.53,19.05 | 145.41,14.61 146.05,15.24 154.31,15.24 155.57,13.97 U$2.BN2 | 145.41,14.61 144.78,13.97 U$2.BT2 | U$2.BC2 184.15,13.97 v182.88,15.24 177.8,15.24 176.53,13.97 U$2.BF2 174.62,13.97 v173.35,15.24 | v144.78,15.24 145.41,14.61
MA00\  (via drill 0.61)
  Top 0.254: v254,69.85 v254,21.59 | v250.82,19.05 250.82,15.88 252.73,13.97 U$2.AD1
  Bottom 0.254: IC4.23 99.69,48.26 100.97,49.53 119.38,49.53 120.65,48.26 IC10.23 120.02,46.36 120.02,40.01 120.65,39.37 148.59,39.37 184.15,74.93 235.59,74.93 240.66,69.85 v254,69.85 | v254,21.59 251.46,19.05 v250.82,19.05
MA01\  (via drill 0.61)
  Top 0.254: IC4.21 104.14,43.18 105.41,44.45 119.38,44.45 120.65,43.18 IC10.21 | v208.91,55.25 v142.88,55.25 | v231.78,47.63 248.92,30.48 248.92,13.97 U$2.AE1
  Bottom 0.254: v142.88,55.25 130.81,43.18 IC10.21 | v208.91,55.25 224.16,55.25 v231.78,47.63
MA02\  (via drill 0.61)
  Top 0.254: v141.6,55.25 153.03,66.68 219.07,66.68 224.79,72.39 227.33,72.39 231.78,67.95 231.78,62.87 232.41,62.23 250.19,62.23 251.46,60.96 251.46,22.86 v252.09,22.23 | v243.21,15.24 243.21,13.97 U$2.AH1
  Bottom 0.254: IC4.24 104.14,50.8 105.41,52.07 119.38,52.07 120.65,50.8 IC10.24 125.09,50.8 127.64,53.34 139.7,53.34 v141.6,55.25 | v252.09,22.23 247.65,22.23 243.21,17.78 v243.21,15.24
MA03\  (via drill 0.61)
  Top 0.254: v87,54.61 100.33,67.95 v194.94,67.95 | v229.87,44.45 232.41,41.91 234.95,41.91 235.59,41.28 235.59,27.31 234.95,26.67 231.78,26.67 228.6,23.5 235.59,16.51 236.22,16.51 238.76,13.97 U$2.AJ1
  Bottom 0.254: IC10.25 120.65,53.34 119.38,54.61 105.41,54.61 104.14,53.34 IC4.25 95.25,53.34 93.98,54.61 v87,54.61 | v194.94,67.95 218.44,44.45 v229.87,44.45
MA04\  (via drill 0.61)
  Top 0.254: v138.43,54.61 141.6,51.44 164.47,51.44 v168.91,46.99 | v175.9,40.01 v175.9,29.85 | v179.07,26.67 179.07,15.88 180.97,13.97 U$2.BD1
  Bottom 0.254: IC4.3 93.98,55.88 95.25,54.61 104.14,54.61 105.41,55.88 IC10.3 119.38,55.88 120.65,54.61 v138.43,54.61 | v168.91,46.99 v175.9,40.01 | v175.9,29.85 v179.07,26.67
MA05\  (via drill 0.61)
  Top 0.254: v127,48.26 125.73,49.53 120.65,49.53 116.84,53.34 IC10.4 | v134.62,48.26 v166.37,48.26 | v174.62,40.01 v174.62,29.85 | v177.8,26.67 177.8,13.97 U$2.BE1
  Bottom 0.254: IC4.4 93.98,53.34 95.25,52.07 104.14,52.07 105.41,53.34 IC10.4 | v127,48.26 v134.62,48.26 | v166.37,48.26 v174.62,40.01 | v174.62,29.85 v177.8,26.67
MA06\  (via drill 0.61)
  Top 0.254: v129.54,33.02 129.54,40.64 123.19,46.99 120.65,46.99 116.84,50.8 IC10.5 | v158.12,24.77 v164.47,24.77 | v170.18,15.24 171.45,13.97 U$2.BH1
  Bottom 0.254: IC4.5 93.98,50.8 95.25,49.53 99.69,49.53 100.33,50.17 106.05,50.17 IC10.5 | v129.54,33.02 144.78,33.02 155.57,22.23 v158.12,24.77 | v164.47,24.77 170.18,19.05 v170.18,15.24
MA07\  (via drill 0.61)
  Top 0.254: v158.12,23.5 v164.47,23.5 | v167,15.24 168.28,13.97 U$2.BJ1
  Bottom 0.254: IC4.6 93.98,48.26 95.25,46.99 104.14,46.99 105.41,48.26 IC10.6 120.02,34.93 120.02,29.85 120.65,29.21 147.32,29.21 154.94,21.59 156.21,21.59 v158.12,23.5 | v164.47,23.5 164.47,17.78 v167,15.24
MA08\  (via drill 0.61)
  Top 0.254: IC4.7 93.98,45.72 95.25,44.45 104.14,44.45 105.41,45.72 IC10.7 | v49.53,15.24 49.53,13.97 U$2.DD1
  Bottom 0.254: v49.53,15.24 80.01,45.72 IC4.7
MA09\  (via drill 0.61)
  Top 0.254: IC10.8 105.41,43.18 104.14,41.91 95.25,41.91 93.98,43.18 IC4.8 v75.56,43.18 | v47.62,15.24 46.35,13.97 U$2.DE1
  Bottom 0.254: v47.62,15.24 v75.56,43.18
MA10\  (via drill 0.61)
  Top 0.254: v41.91,15.88 40.01,13.97 U$2.DH1 | v69.85,40.64 IC4.9
  Bottom 0.254: IC4.9 93.98,40.64 95.25,41.91 104.14,41.91 105.41,40.64 IC10.9 | v69.85,40.64 45.09,15.88 v41.91,15.88
MA11\  (via drill 0.61)
  Top 0.254: IC10.10 105.41,38.1 104.14,39.37 95.25,39.37 93.98,38.1 IC4.10 v66.04,38.1 | v40.64,17.78 36.83,13.97 U$2.DJ1
  Bottom 0.254: v66.04,38.1 45.72,17.78 v40.64,17.78
MD00\  (via drill 0.61)
  Top 0.254: v236.22,15.24 236.22,13.97 U$2.AK1
  Bottom 0.254: v236.22,15.24 236.22,40.64 234.95,41.91 232.41,41.91 231.14,40.64 E1.2
MD01\  (via drill 0.61)
  Top 0.254: v234.95,15.24 233.68,13.97 U$2.AL1
  Bottom 0.254: v234.95,15.24 235.59,15.88 235.59,38.74 E1.15
MD02\
  Top 0.254: E1.7 224.16,26.04 224.16,19.05 229.24,13.97 U$2.AM1
MD03\  (via drill 0.61)
  Top 0.254: v224.16,15.88 224.16,13.97 U$2.AP1
  Bottom 0.254: E1.9 v224.16,15.88
MD04\  (via drill 0.61)
  Top 0.254: v154.94,31.75 153.03,33.66 153.03,38.74 E2.2 | v163.19,15.88 165.1,13.97 U$2.BK1
  Bottom 0.254: v154.94,31.75 159.38,31.75 163.19,27.94 v163.19,15.88
MD05\  (via drill 0.61)
  Top 0.254: v160.66,29.21 160.66,38.74 E2.15 | v160.66,15.24 161.93,13.97 U$2.BL1
  Bottom 0.254: v160.66,15.24 v160.66,29.21
MD06\  (via drill 0.61)
  Top 0.254: v159.38,15.24 159.38,13.97 U$2.BM1
  Bottom 0.254: v159.38,15.24 159.38,28.58 E2.7
MD07\  (via drill 0.61)
  Top 0.254: v158.12,26.04 160.02,27.94 E2.9 | v155.57,23.5 155.57,15.24 154.31,13.97 U$2.BP1
  Bottom 0.254: v155.57,23.5 v158.12,26.04
MD08\  (via drill 0.61)
  Top 0.254: v26.67,21.59 29.21,21.59 33.66,17.15 33.66,13.97 U$2.DK1
  Bottom 0.254: v26.67,21.59 20.95,27.31 20.95,41.28 E3.2
MD09\  (via drill 0.61)
  Top 0.254: v32.38,17.15 29.21,13.97 U$2.DL1
  Bottom 0.254: v32.38,17.15 32.38,41.28 E3.15
MD10\  (via drill 0.61)
  Top 0.254: v25.4,24.13 25.4,13.97 U$2.DM1
  Bottom 0.254: v25.4,24.13 25.4,27.94 E3.7
MD11\  (via drill 0.61)
  Top 0.254: v21.59,15.24 20.32,13.97 U$2.DP1
  Bottom 0.254: v21.59,15.24 29.84,23.5 29.84,27.31 E3.9
MEM00  (via drill 0.61)
  Top 0.254: v158.12,20.96 169.54,20.96 184.15,35.56 v184.15,40.01 | E1.4 208.28,35.56 206.38,33.66 205.1,33.66 202.56,36.2 202.56,43.82 IC1.18
  Bottom 0.254: v158.12,20.96 157.48,20.32 153.67,20.32 151.76,22.23 109.86,22.23 104.14,27.94 IC4.15 | v184.15,40.01 188.59,44.45 198.12,44.45 199.39,45.72 IC1.18
MEM01  (via drill 0.61)
  Top 0.254: v158.12,22.23 169.54,22.23 v181.61,34.29
  Bottom 0.254: v158.12,22.23 156.84,20.96 154.31,20.96 152.4,22.86 124.46,22.86 118.11,29.21 95.25,29.21 93.98,30.48 IC4.13 | v181.61,34.29 194.31,34.29 199.39,39.37 | 199.39,39.37 IC1.16 | 199.39,39.37 227.33,39.37 231.14,35.56 E1.13
MEM02  (via drill 0.61)
  Top 0.254: v158.12,19.69 169.54,19.69 v179.07,29.21 | E1.5 204.47,33.02 201.93,35.56 IC1.14
  Bottom 0.254: v158.12,19.69 153.03,19.69 151.13,21.59 85.09,21.59 79.38,27.31 79.38,31.12 IC4.12 | v179.07,29.21 194.31,29.21 IC1.14
MEM03  (via drill 0.61)
  Top 0.254: v231.14,33.02 E1.11 | v115.57,36.83 127.64,36.83 v128.27,37.47 | v207.01,36.83 v207.01,44.45
  Bottom 0.254: v231.14,33.02 227.33,36.83 v207.01,36.83 205.74,36.83 204.47,35.56 204.47,34.29 IC1.12 | v115.57,36.83 95.25,36.83 93.98,35.56 IC4.11 | v128.27,37.47 149.22,37.47 156.21,44.45 161.29,44.45 166.37,49.53 201.93,49.53 v207.01,44.45
MEM04  (via drill 0.61)
  Top 0.254: v186.69,37.47 186.69,35.56 191.77,30.48 IC1.9
  Bottom 0.254: IC10.19 126.36,38.1 128.27,36.2 154.31,36.2 156.21,38.1 E2.4 158.75,38.1 160.02,39.37 166.37,39.37 168.91,36.83 186.06,36.83 v186.69,37.47
MEM05
  Bottom 0.254: IC10.18 154.94,35.56 156.21,36.83 162.56,36.83 163.83,38.1 E2.13 167.64,35.56 IC1.7
MEM06  (via drill 0.61)
  Top 0.254: v154.31,33.66 156.21,35.56 E2.5 | IC10.17 v128.27,33.02 | v167.64,36.83 163.19,36.83 v161.93,35.56
  Bottom 0.254: v128.27,33.02 129.54,34.29 153.67,34.29 v154.31,33.66 | v167.64,36.83 168.28,36.2 187.32,36.2 191.77,40.64 IC1.5 | E2.5 v161.93,35.56
MEM07  (via drill 0.61)
  Top 0.254: v175.26,41.91 166.37,33.02 E2.11
  Bottom 0.254: IC10.16 124.46,30.48 128.91,34.93 155.57,34.93 156.21,34.29 162.56,34.29 163.83,33.02 E2.11 | v175.26,41.91 179.07,45.72 IC1.3
MEM08  (via drill 0.61)
  Top 0.254: v26.67,38.1 27.94,38.1 29.21,39.37 41.91,39.37 44.45,41.91 48.26,41.91 52.07,45.72 IC2.18
  Bottom 0.254: E3.4 v26.67,38.1 | IC10.15 120.65,27.94 116.84,31.75 116.84,36.83 109.22,44.45 85.09,44.45 82.55,46.99 55.88,46.99 54.61,45.72 IC2.18
MEM09  (via drill 0.61)
  Top 0.254: E3.13 43.18,38.1 44.45,39.37 50.8,39.37 52.07,40.64 IC2.16 54.61,40.64 59.69,35.56 v71.12,35.56
  Bottom 0.254: v71.12,35.56 72.39,34.29 97.79,34.29 101.6,30.48 IC10.13
MEM10  (via drill 0.61)
  Top 0.254: v26.04,36.2 27.3,36.2 29.21,34.29 41.91,34.29 44.45,36.83 50.8,36.83 52.07,35.56 IC2.14 54.61,35.56 55.88,34.29 82.55,34.29 87.63,29.21 97.79,29.21 101.6,33.02 IC10.12
  Bottom 0.254: v26.04,36.2 25.4,35.56 E3.5
MEM11
  Top 0.254: 50.8,31.75 52.07,30.48 IC2.12 | 50.8,31.75 48.26,34.29 44.45,34.29 43.18,33.02 E3.11 | 50.8,31.75 82.55,31.75 87.63,26.67 97.79,26.67 100.33,29.21 107.95,29.21 108.58,29.85 108.58,33.66 IC10.11
MINE\
  Top 0.254: D8.A 258.44,56.52 258.44,57.79 D7.A 258.44,59.06 258.44,60.33 D6.A 258.44,61.6 258.44,62.87 D5.A 258.44,64.14 258.44,65.41 D4.A 258.44,66.68 258.44,67.95 D3.A 258.44,69.22 258.44,70.49 D2.A 258.44,71.76 258.44,73.03 D1.A | IC3.5 20.95,65.41 20.95,66.68 IC3.3 | IC4.20 104.14,40.64 105.41,41.91 119.38,41.91 120.65,40.64 IC10.20 R1.1
  Bottom 0.254: 48.26,64.77 134.62,64.77 144.15,55.25 | 48.26,64.77 29.21,64.77 25.4,68.58 IC3.3 | 144.15,55.25 129.54,40.64 R1.1 | 144.15,55.25 164.47,75.57 249.56,75.57 251.46,73.66 D1.A | 48.26,64.77 IC5.9
N$1  (via drill 0.61)
  Top 0.254: v231.14,53.34 238.12,53.34 240.66,55.88 SV2.2
  Bottom 0.254: IC9.7 v231.14,53.34
N$18
  Top 0.254: IC9.9 238.12,55.88 240.66,58.42 SV2.4
N$19
  Top 0.254: IC9.10 238.12,58.42 240.66,60.96 SV2.6
N$20
  Bottom 0.254: IC9.11 238.12,60.96 240.66,63.5 SV2.8
N$21
  Top 0.254: IC9.12 238.12,63.5 240.66,66.04 SV2.10
N$22
  Top 0.254: IC9.13 238.12,66.04 240.66,68.58 SV2.12
N$23
  Top 0.254: IC9.14 238.12,68.58 240.66,71.12 SV2.14
N$24
  Top 0.254: IC9.15 238.12,71.12 240.66,73.66 SV2.16
N$25
  Top 0.254: C1.1 R3.2 IC5.7
N$26
  Top 0.254: SV2.1 D8.C
N$27
  Top 0.254: SV2.3 D7.C
N$28
  Top 0.254: SV2.5 D6.C
N$29
  Top 0.254: SV2.7 D5.C
N$30
  Top 0.254: SV2.9 D4.C
N$31
  Top 0.254: SV2.11 D3.C
N$32
  Top 0.254: SV2.13 D2.C
N$33
  Top 0.254: SV2.15 D1.C
N$34
  Top 0.254: C1.2 43.18,66.04 45.72,63.5 IC5.6
N$35
  Top 0.254: IC4.16 95.89,31.12 95.89,32.39 IC4.17 95.89,33.66 95.89,34.93 IC4.18 95.89,36.2 95.89,37.47 IC4.19 R2.1
READ  (via drill 0.61)
  Top 0.254: IC3.1 24.77,71.76 24.77,62.87 IC3.6 | 127,58.42 135.89,58.42 140.97,53.34 209.55,53.34 218.44,62.23 227.33,62.23 227.97,61.6 227.97,42.55 229.24,41.28 229.24,37.47 E1.12 | 127,58.42 v126.36,58.42 | v101.6,58.42 105.41,62.23 123.19,62.23 127,58.42
  Bottom 0.254: E1.12 232.41,33.02 228.6,29.21 210.82,29.21 205.74,24.13 192.41,24.13 191.13,25.4 176.53,25.4 166.37,35.56 E2.12 | 24.77,49.53 24.77,59.06 IC3.6 | 24.77,49.53 24.77,41.28 E3.12 | 79.38,49.53 24.77,49.53 | 79.38,49.53 v86.36,49.53 | 79.38,49.53 79.38,56.52 80.01,57.15 100.33,57.15 v101.6,58.42
ROM_ADDR\  (via drill 0.61)
  Top 0.254: v205.74,35.56 205.74,44.45 207.01,45.72 210.82,45.72 IC9.6 | v205.74,25.4 v205.74,21.59
  Bottom 0.254: v205.74,35.56 v205.74,25.4 | v205.74,21.59 205.74,20.32 209.55,16.51 209.55,13.97 U$2.AU2
VCC  (via drill 0.61)
  Top 0.762: 185.42,45.72 191.77,52.07 198.12,52.07 199.39,50.8 IC1.20 v214.63,50.8 | 185.42,45.72 E2.16 160.02,45.72 158.75,46.99 130.18,46.99 | v190.5,22.86 190.5,30.48 185.42,35.56 185.42,45.72 | 100.33,57.15 101.6,55.88 R2.2 | 100.33,57.15 IC4.28 | 100.33,57.15 107.95,57.15 111.76,60.96 IC10.28 127,55.88 R1.2 127,50.17 130.18,46.99 | v128.27,19.05 128.27,29.85 130.81,32.39 130.81,46.36 130.18,46.99 | IC3.14 37.47,73.66 40.01,71.12 R3.1 41.27,71.12 45.09,67.31 52.7,67.31 | 46.99,55.88 52.7,61.6 | 46.99,55.88 36.83,45.72 E3.16 | 52.7,61.6 IC5.11 | 52.7,61.6 52.7,67.31 | 52.7,67.31 52.7,74.3 IC5.16 | 46.99,55.88 52.07,50.8 IC2.20
  Bottom 0.762: v190.5,22.86 190.5,13.97 U$2.BA2 | 233.04,44.45 233.04,43.82 E1.16 234.95,43.18 260.35,17.78 260.35,13.97 U$2.AA2 | 233.04,44.45 233.04,53.98 227.97,59.06 227.97,67.95 IC9.16 | v128.27,19.05 128.27,13.97 U$2.CA2 | IC2.20 71.12,50.8 80.01,59.69 93.98,59.69 95.25,60.96 IC4.28 | v214.63,50.8 226.69,50.8 233.04,44.45
WRITE  (via drill 0.61)
  Top 0.254: IC10.22 120.65,45.72 119.38,46.99 105.41,46.99 104.14,45.72 IC4.22 95.25,45.72 93.98,46.99 68.58,46.99 | 48.26,50.8 52.07,46.99 68.58,46.99 | 68.58,46.99 IC5.10 | v132.08,45.72 151.13,45.72 v154.94,41.91 | v161.29,41.91 163.83,44.45 173.99,44.45 177.16,41.28 v177.16,34.29 | v204.47,27.94 209.55,27.94 214.63,22.86 v214.63,15.24
  Bottom 0.254: v154.94,41.91 v161.29,41.91 | v177.16,34.29 174.62,34.29 172.09,31.75 173.35,30.48 173.99,30.48 174.62,31.12 175.9,31.12 180.34,26.67 203.2,26.67 v204.47,27.94 | v214.63,15.24 215.9,13.97 U$2.AS2 | IC10.22 v132.08,45.72
WRITEM  (via drill 0.61)
  Top 0.254: IC1.1 196.85,50.8 199.39,48.26 IC1.19 | v192.41,70.49 89.53,70.49 v81.92,62.87
  Bottom 0.254: IC3.4 24.13,66.04 27.94,62.23 31.75,62.23 43.18,50.8 IC2.1 49.53,50.8 61.59,62.87 v81.92,62.87 | v192.41,70.49 192.41,51.44 IC1.1
WRITEP\
  Top 0.254: IC10.27 120.65,58.42 116.84,54.61 105.41,54.61 104.78,53.98 104.78,49.53 102.23,46.99 100.97,46.99 100.33,47.63 100.33,54.61 IC4.27 92.08,58.42 85.72,52.07 69.85,52.07 55.88,66.04 IC5.12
